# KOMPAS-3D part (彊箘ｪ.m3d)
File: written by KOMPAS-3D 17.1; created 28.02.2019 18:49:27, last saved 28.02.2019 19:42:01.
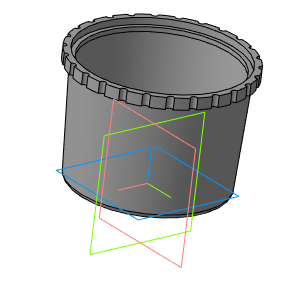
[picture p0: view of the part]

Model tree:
1. Эскиз:1
2. Элемент вращения:1
     Угол 1 = 360
3. Скругление:1
     Радиус = 2
4. Эскиз:2
5. Элемент вращения:2
     Угол 1 = 360
6. Массив по концентрической сетке:1  (with: Элемент вращения:2)  (26 pattern instances)
     Шаг 2 = 360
